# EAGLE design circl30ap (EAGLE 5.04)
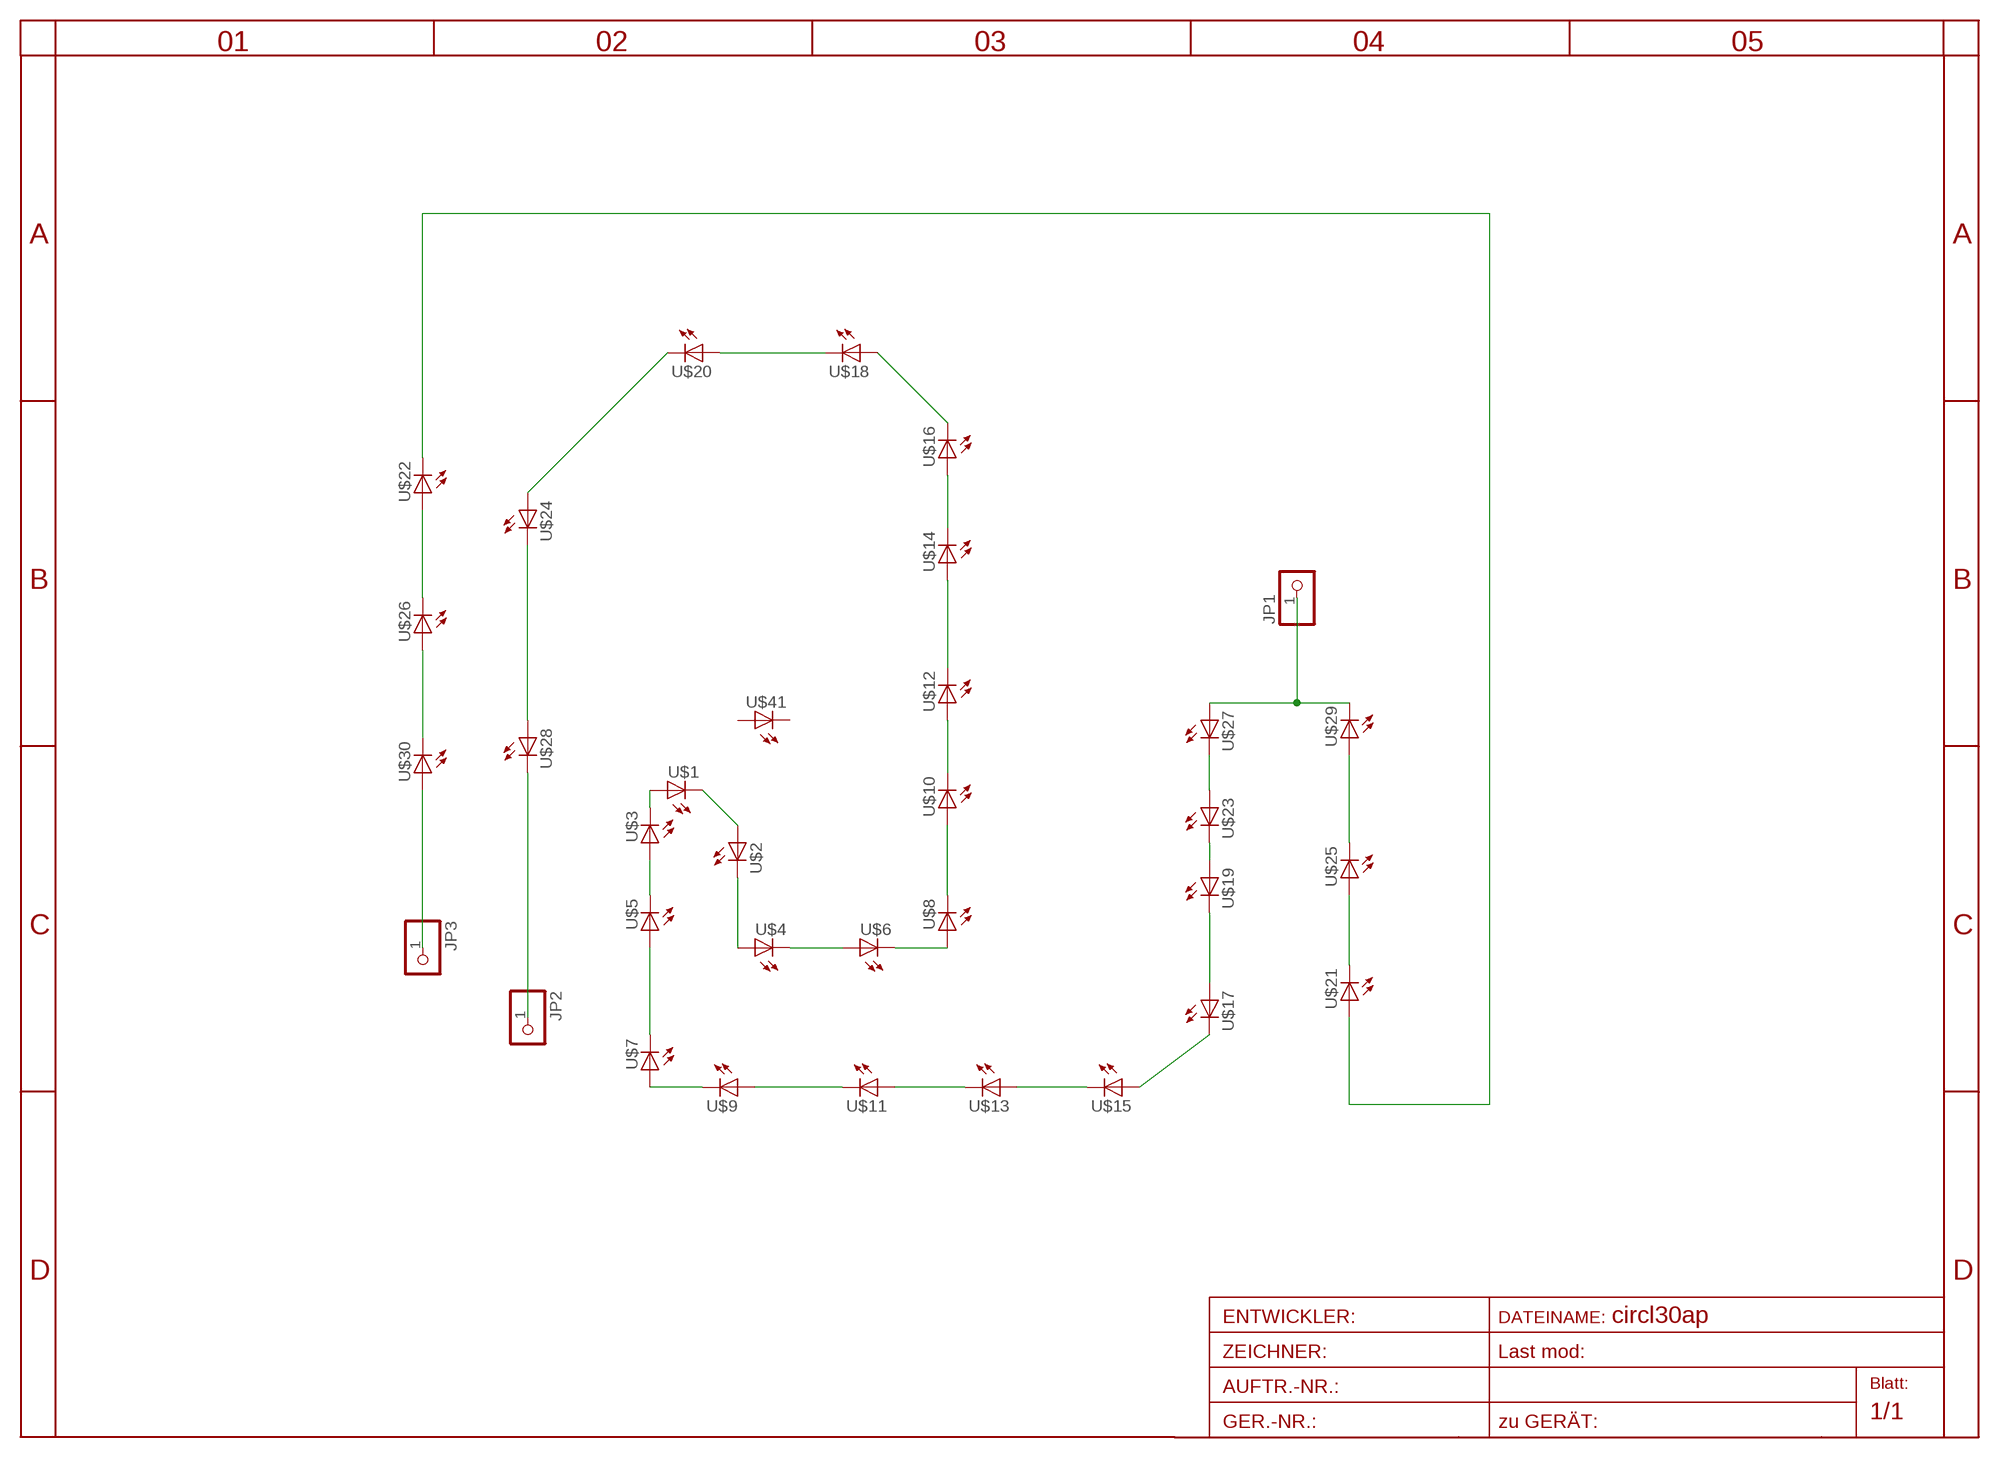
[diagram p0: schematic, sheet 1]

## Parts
JP1  PINHD-1X1  [1X01]
JP2  PINHD-1X1  [1X01]
JP3  PINHD-1X1  [1X01]
U$1  LED5MM  [LED5MM]
U$2  LED5MM  [LED5MM]
U$3  LED5MM  [LED5MM]
U$4  LED5MM  [LED5MM]
U$5  LED5MM  [LED5MM]
U$6  LED5MM  [LED5MM]
U$7  LED5MM  [LED5MM]
U$8  LED5MM  [LED5MM]
U$9  LED5MM  [LED5MM]
U$10  LED5MM  [LED5MM]
U$11  LED5MM  [LED5MM]
U$12  LED5MM  [LED5MM]
U$13  LED5MM  [LED5MM]
U$14  LED5MM  [LED5MM]
U$15  LED5MM  [LED5MM]
U$16  LED5MM  [LED5MM]
U$17  LED5MM  [LED5MM]
U$18  LED5MM  [LED5MM]
U$19  LED5MM  [LED5MM]
U$20  LED5MM  [LED5MM]
U$21  LED5MM  [LED5MM]
U$22  LED5MM  [LED5MM]
U$23  LED5MM  [LED5MM]
U$24  LED5MM  [LED5MM]
U$25  LED5MM  [LED5MM]
U$26  LED5MM  [LED5MM]
U$27  LED5MM  [LED5MM]
U$28  LED5MM  [LED5MM]
U$29  LED5MM  [LED5MM]
U$30  LED5MM  [LED5MM]
U$41  LED5MM  [LED5MM]

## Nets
N$1: U$10.K(C) U$12.A
N$2: U$25.K(C) U$29.A
N$3: JP1.1 U$27.A U$29.K(C)
N$4: U$20.K(C) U$24.A
N$5: U$24.K(C) U$28.A
N$6: U$12.K(C) U$14.A
N$7: U$14.K(C) U$16.A
N$8: U$16.K(C) U$18.A
N$9: U$18.K(C) U$20.A
N$10: U$22.A U$26.K(C)
N$11: U$8.K(C) U$10.A
N$12: U$6.K(C) U$8.A
N$13: U$4.K(C) U$6.A
N$14: U$2.K(C) U$4.A
N$15: U$1.K(C) U$2.A
N$16: U$1.A U$3.K(C)
N$17: U$3.A U$5.K(C)
N$18: U$5.A U$7.K(C)
N$19: U$7.A U$9.K(C)
N$20: U$9.A U$11.K(C)
N$21: U$11.A U$13.K(C)
N$22: U$13.A U$15.K(C)
N$23: U$15.A U$17.K(C)
N$24: U$17.A U$19.K(C)
N$25: U$21.K(C) U$25.A
N$26: JP3.1 U$30.A
N$27: U$26.A U$30.K(C)
N$28: U$23.A U$27.K(C)
N$29: U$19.A U$23.K(C)
N$30: JP2.1 U$28.K(C)
N$31: U$21.A U$22.K(C)
Unconnected: U$41.A U$41.K(C)

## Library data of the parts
JP1-JP3 = pinhead:PINHD-1X1: PIN HEADER
U$1-U$30 U$41 = led(2):LED: LED

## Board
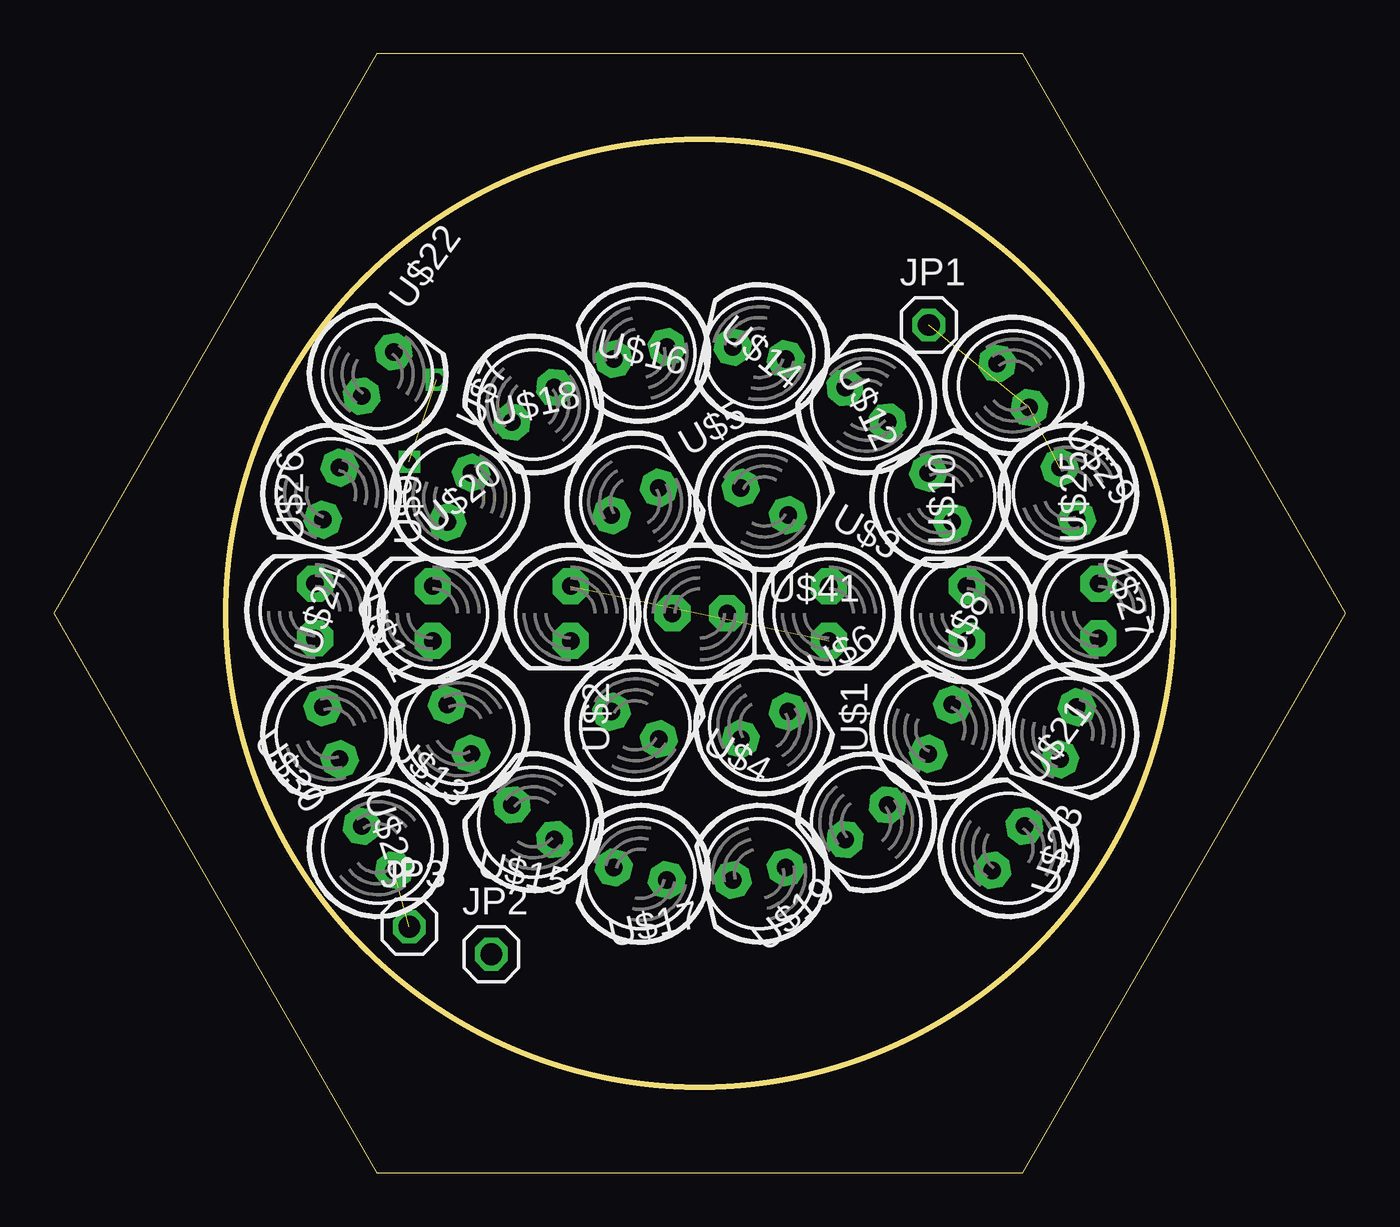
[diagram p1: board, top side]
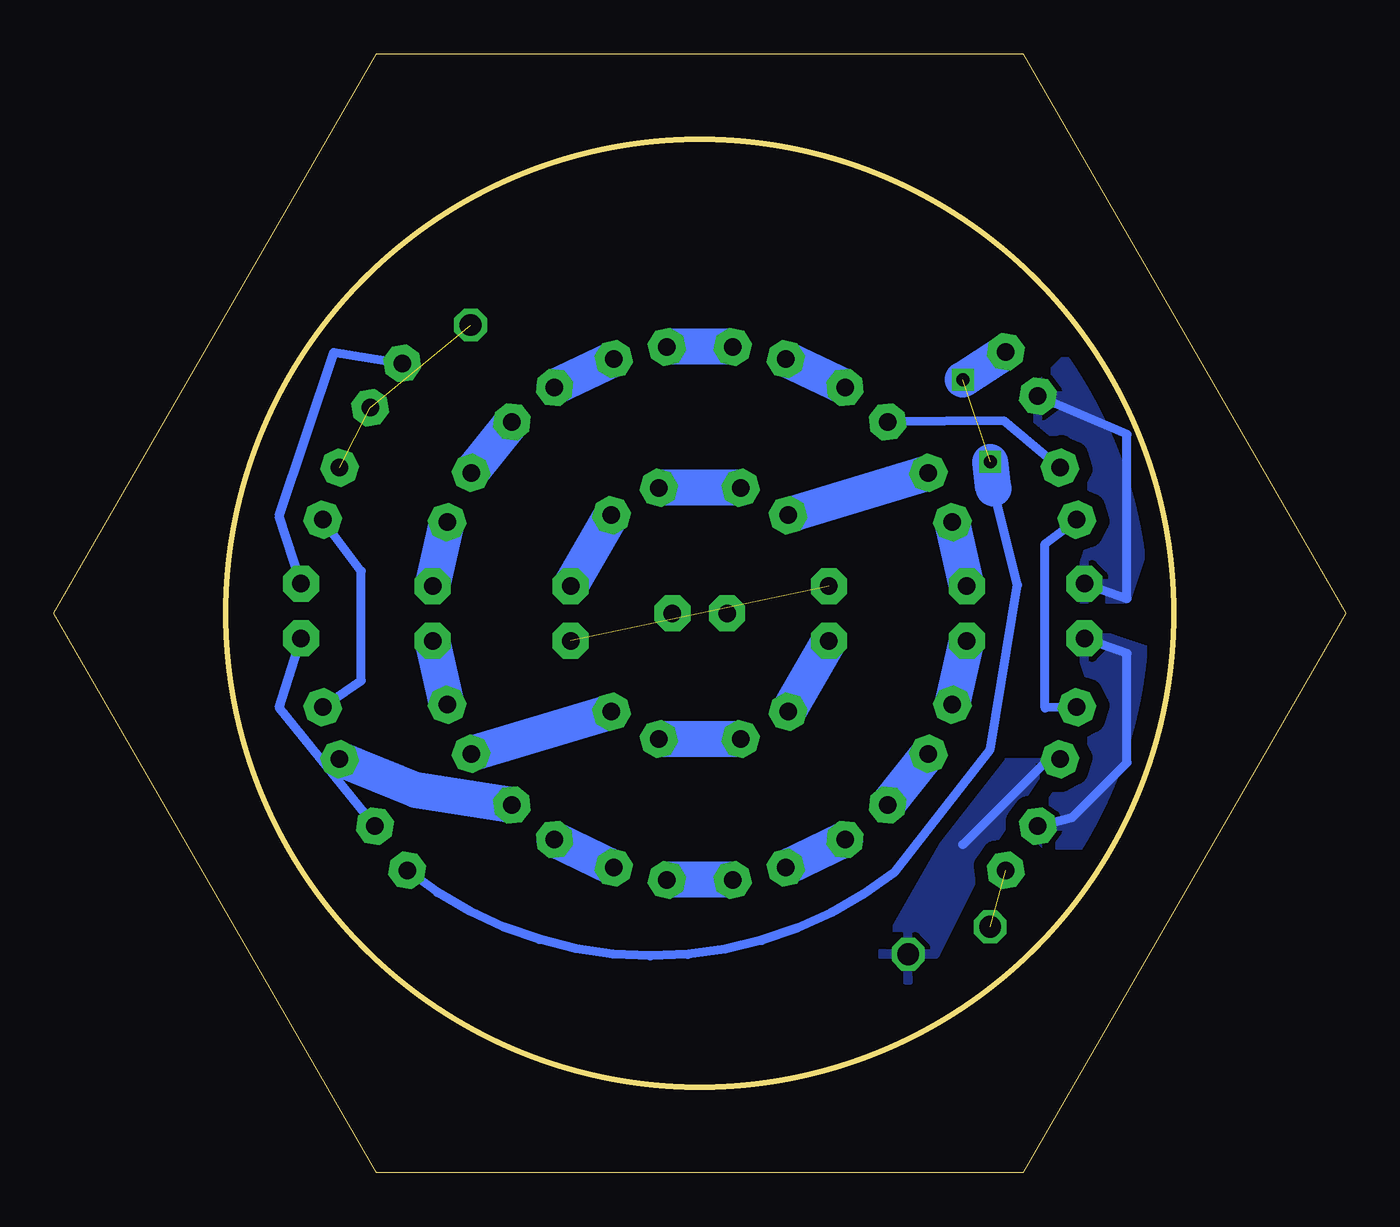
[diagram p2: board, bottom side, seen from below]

Size 60 x 51.96 mm. Coordinates in mm from the lower left corner, seen from the top.
Outline: 15,0 45,0 60,25.98 45,51.96 15,51.96 0,25.98 15,0
Outline: circle at 30,25.98 radius 22
Copper layers (1*16): Top 0.035mm / dielectric 1.5mm / Bottom 0.035mm
Design rules "default": minimum track width 10mil, minimum drill 24mil, track to track 8mil, track to pad 8mil, pad to pad 8mil, via to via 8mil, smd to smd 8mil, copper to edge 40mil, drill to drill 8mil, minimum pad ring 10mil, minimum via ring 8mil, stop-mask expansion 4mil, vias tented up to drill 0mil, thermal gap 10mil

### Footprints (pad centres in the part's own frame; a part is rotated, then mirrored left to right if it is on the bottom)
1X01 = drill 1.016 octagon: 1 0,0
LED5MM = drill 0.813 pad 1.676 octagon: A -1.27,0; K 1.27,0

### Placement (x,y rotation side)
JP1  40.64,39.37 0 top
JP2  20.32,10.16 0 top
JP3  16.51,11.43 0 top
U$1  36,25.98 270 top
U$2  24,25.98 270 top
U$3  33,31.18 330 top
U$4  27,20.78 330 top
U$5  27,31.18 30 top
U$6  33,20.78 30 top
U$7  18.83,31.36 64 top
U$8  41.17,20.6 64 top
U$9  17.6,25.98 90 top
U$10  42.4,25.98 90 top
U$11  18.83,20.6 116 top
U$12  41.17,31.36 116 top
U$13  22.27,16.29 141 top
U$14  37.73,35.67 141 top
U$15  27.24,13.89 167 top
U$16  32.76,38.07 167 top
U$17  32.76,13.89 193 top
U$18  27.24,38.07 193 top
U$19  37.73,16.29 219 top
U$20  22.27,35.67 219 top
U$21  44.34,15.08 54 top
U$22  15.04,37.1 54 top
U$23  47.12,20.42 252 top
U$24  12.88,31.54 252 top
U$25  48.52,26.09 90 top
U$26  12.13,26.09 90 top
U$27  47.12,31.54 288 top
U$28  12.88,20.42 288 top
U$29  44.56,36.56 306 top
U$30  15.04,15.08 126 top
U$41  30,25.98 0 top

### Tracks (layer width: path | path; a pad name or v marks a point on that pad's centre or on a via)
N$1
  Bottom 1.676: U$10.K U$12.A
N$2
  Bottom 0.406: U$29.A 46.99,38.1 49.53,30.48 U$25.K
N$3  (2 unrouted)
N$4
  Bottom 0.406: U$24.A 15.88,34.92 U$20.K
N$5
  Bottom 0.406: U$28.A 13.97,21.59 13.97,29.21 U$24.K
N$6
  Bottom 1.676: U$12.K U$14.A
N$7
  Bottom 1.676: U$16.A U$14.K
N$8
  Bottom 1.676: U$18.A U$16.K
N$9
  Bottom 1.676: U$20.A U$18.K
N$10
  Bottom 0.406: U$22.A 10.16,34.29 10.16,26.67 U$26.K
  pour Bottom (isolate 0.61, rank 2): 12.7,26.67 10.16,26.67 8.89,30.48 12.7,38.1 15.24,35.56 12.7,33.02 11.43,30.48
N$11
  Bottom 1.676: U$8.K U$10.A
N$12
  Bottom 1.676: U$6.K U$8.A
N$13
  Bottom 1.676: U$4.K U$6.A
N$14
  Bottom 1.676: U$2.K U$4.A
N$15  (1 unrouted)
N$16
  Bottom 1.676: U$1.A U$3.K
N$17
  Bottom 1.676: U$5.K U$3.A
N$18
  Bottom 1.676: U$7.K U$5.A
N$19
  Bottom 1.676: U$9.K U$7.A
N$20
  Bottom 1.676: U$11.K U$9.A
N$21
  Bottom 1.676: U$13.K U$11.A
N$22
  Bottom 1.676: U$15.K U$13.A
N$23
  Bottom 1.676: U$15.A U$17.K
N$24
  Bottom 1.676: U$17.A U$19.K
N$25
  Bottom 0.406: U$25.A 49.53,21.59 U$21.K
N$26  (1 unrouted)
N$27
  Bottom 0.406: U$26.A 10.16,24.13 10.16,19.05 12.7,16.51 U$30.K
  pour Bottom (isolate 0.61, rank 2): 13.97,15.24 11.43,15.24 8.89,24.13 12.7,25.4 11.43,21.59 15.24,16.51
N$28
  Bottom 0.406: U$23.A 45.72,22.86 45.72,27.94 U$27.K
N$29
  Bottom 1.676: U$23.K 43.18,17.78 U$19.A
N$30
  Bottom 0.406: 17.78,15.24 13.97,19.05 U$28.K
  pour Bottom (isolate 0.61): 13.97,19.05 16.51,19.05 21.59,10.16 20.32,8.89 19.05,10.16 16.51,15.24
N$31  (via drill 0.6)  (1 unrouted)
  Bottom 0.406: U$21.A arc-77 20.95,13.97 16.51,19.68 15.24,27.3 16.35,31.77
  Bottom 1.676: U$22.K v17.78,36.83 | 16.35,31.77 v16.51,33.02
